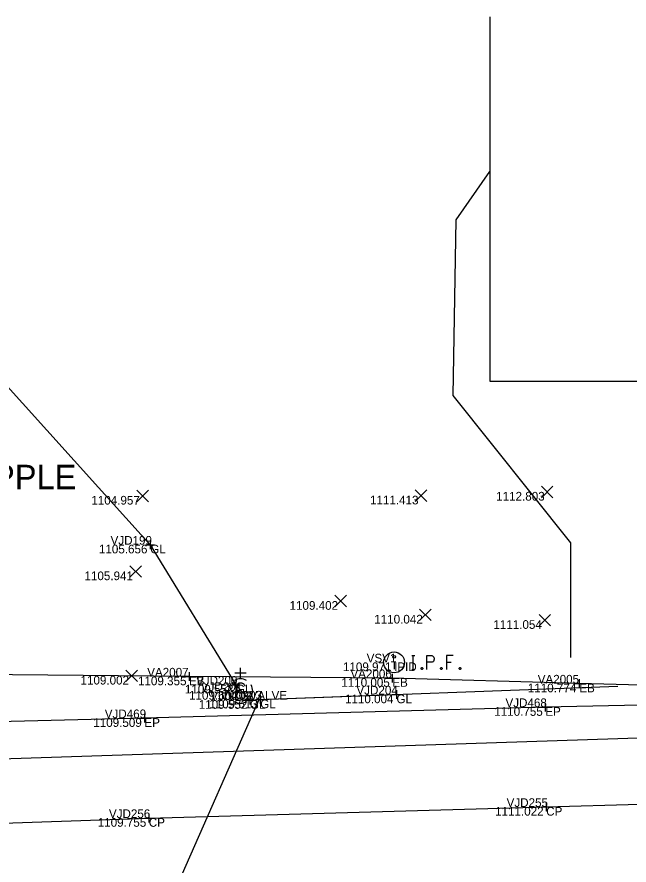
# Model space of a CAD drawing. Extents: x 1629915 to 1630675, y 484401 to 484601.
# Drawn here: x 1630425.3 to 1630495.7, y 484489.5 to 484587 of the extents above; entities that cross this region are included whole.
import ezdxf

# ---------------------------------------------------------------- set-up
doc = ezdxf.new("R2010")
doc.units = 0
for name, color, linetype in [('BD_X_Building', 7, 'Continuous'), ('PV_X_COP', 7, 'Continuous'), ('PV_X_EOP', 7, 'Continuous'), ('PV_X_Shoulder_Aggregate', 7, 'Continuous'), ('SV_X_Mon_Cells_Found', 7, 'Continuous'), ('SV_X_Random_Point', 7, 'Continuous'), ('SV_X_Shot_Marker', 7, 'Continuous'), ('SV_X_Text_Comment', 7, 'Continuous'), ('SV_X_Text_Elevation', 7, 'Continuous'), ('SV_X_Text_Name', 7, 'Continuous'), ('TX_X_20', 7, 'Continuous'), ('UT_X_Gas', 7, 'Continuous'), ('UT_X_Gas_Cells', 7, 'Continuous'), ('UT_X_Sanitary_Line', 7, 'Continuous')]:
    doc.layers.add(name, color=color, linetype=linetype)

msp = doc.modelspace()

# ---------------------------------------------------------------- linework, layer by layer
at = {"layer": 'BD_X_Building'}
msp.add_lwpolyline([(1630479.655, 484587.031), (1630479.655, 484545.173), (1630505.564, 484545.173), (1630505.564, 484546.173), (1630541.342, 484546.173), (1630541.342, 484585.235)], dxfattribs=at)
at = {"layer": 'PV_X_COP'}
msp.add_lwpolyline([(1630297.366, 484489.973), (1630308.553, 484490.492), (1630361.839, 484492.402), (1630403.565, 484493.662), (1630440.464, 484494.931), (1630486.149, 484496.207), (1630529.234, 484497.459), (1630568.325, 484498.484), (1630611.926, 484499.834), (1630649.713, 484500.97)], dxfattribs=at)
at = {"layer": 'PV_X_EOP'}
msp.add_lwpolyline([(1630649.544, 484512.337), (1630611.095, 484510.961), (1630568.311, 484509.618), (1630527.921, 484508.555), (1630486.049, 484507.685), (1630439.965, 484506.412), (1630403.104, 484505.478), (1630361.875, 484504.434), (1630301.74, 484502.192)], dxfattribs=at)
at = {"layer": 'PV_X_Shoulder_Aggregate'}
msp.add_lwpolyline([(1630609.295, 484512.622), (1630601.375, 484512.79), (1630594.371, 484513.028), (1630564.661, 484511.714), (1630557.668, 484510.64), (1630535.062, 484510.052), (1630513.96, 484509.735), (1630489.956, 484510.39), (1630468.462, 484511.02), (1630445.091, 484511.198), (1630420.706, 484511.45), (1630393.49, 484511.943), (1630369.145, 484512.288), (1630344.7, 484511.845), (1630320.659, 484510.608), (1630304.125, 484509.436), (1630303.965, 484508.981)], dxfattribs=at)
at = {"layer": 'SV_X_Mon_Cells_Found'}
msp.add_line((1630468.666, 484512.941), (1630468.666, 484512.058), dxfattribs=at)
for points in [[(1630470.696, 484513.624), (1630471.049, 484513.624)], [(1630470.872, 484512.024), (1630470.872, 484513.624)], [(1630472.438, 484512.024), (1630472.438, 484513.624), (1630472.967, 484513.624), (1630473.022, 484513.612), (1630473.099, 484513.586), (1630473.132, 484513.561), (1630473.165, 484513.536), (1630473.209, 484513.473), (1630473.242, 484513.41), (1630473.264, 484513.309), (1630473.264, 484513.158), (1630473.253, 484513.108), (1630473.231, 484513.032), (1630473.187, 484512.944), (1630473.143, 484512.906), (1630473.11, 484512.881), (1630473.055, 484512.856), (1630472.967, 484512.843), (1630472.438, 484512.843)], [(1630475.447, 484513.624), (1630474.686, 484513.624), (1630474.686, 484512.024)], [(1630471.831, 484512.239), (1630471.887, 484512.239), (1630471.92, 484512.213), (1630471.953, 484512.163), (1630471.953, 484512.1), (1630471.92, 484512.05), (1630471.887, 484512.024), (1630471.831, 484512.024), (1630471.798, 484512.05), (1630471.765, 484512.1), (1630471.765, 484512.163), (1630471.798, 484512.213), (1630471.831, 484512.239)], [(1630474.08, 484512.239), (1630474.135, 484512.239), (1630474.168, 484512.213), (1630474.201, 484512.163), (1630474.201, 484512.1), (1630474.168, 484512.05), (1630474.135, 484512.024), (1630474.08, 484512.024), (1630474.047, 484512.05), (1630474.014, 484512.1), (1630474.014, 484512.163), (1630474.047, 484512.213), (1630474.08, 484512.239)], [(1630474.686, 484512.843), (1630475.227, 484512.843)], [(1630476.23, 484512.239), (1630476.285, 484512.239), (1630476.318, 484512.213), (1630476.351, 484512.163), (1630476.351, 484512.1), (1630476.318, 484512.05), (1630476.285, 484512.024), (1630476.23, 484512.024), (1630476.196, 484512.05), (1630476.163, 484512.1), (1630476.163, 484512.163), (1630476.196, 484512.213), (1630476.23, 484512.239)], [(1630470.696, 484512.024), (1630471.049, 484512.024)]]:
    msp.add_lwpolyline(points, dxfattribs=at)
for centre, radius in [((1630468.666, 484512.824), 1.2), ((1630468.666, 484513.476), 0.16)]:
    msp.add_circle(centre, radius, dxfattribs=at)
at = {"layer": 'SV_X_Random_Point'}
for p, q in [((1630485.595, 484531.761), (1630486.928, 484533.096)), ((1630485.595, 484533.096), (1630486.928, 484531.761)), ((1630439.087, 484531.301), (1630440.421, 484532.636)), ((1630439.087, 484532.636), (1630440.421, 484531.301)), ((1630471.089, 484531.324), (1630472.423, 484532.659)), ((1630471.089, 484532.659), (1630472.423, 484531.324)), ((1630438.283, 484522.613), (1630439.617, 484523.948)), ((1630438.283, 484523.948), (1630439.617, 484522.613)), ((1630461.852, 484519.209), (1630463.186, 484520.544)), ((1630461.852, 484520.544), (1630463.186, 484519.209)), ((1630471.589, 484517.627), (1630472.922, 484518.962)), ((1630471.589, 484518.962), (1630472.922, 484517.627)), ((1630485.331, 484517.014), (1630486.664, 484518.349)), ((1630485.331, 484518.349), (1630486.664, 484517.014)), ((1630437.82, 484510.614), (1630439.154, 484511.949)), ((1630437.82, 484511.949), (1630439.154, 484510.614))]:
    msp.add_line(p, q, dxfattribs=at)
at = {"layer": 'SV_X_Shot_Marker'}
for p, q in [((1630440.635, 484526.86), (1630440.635, 484525.86)), ((1630440.135, 484526.36), (1630441.135, 484526.36)), ((1630440.635, 484526.36), (1630440.635, 484526.36)), ((1630445.091, 484511.698), (1630445.091, 484510.698)), ((1630468.462, 484511.52), (1630468.462, 484510.52)), ((1630444.591, 484511.198), (1630445.591, 484511.198)), ((1630445.091, 484511.198), (1630445.091, 484511.198)), ((1630450.487, 484510.753), (1630450.487, 484509.753)), ((1630467.962, 484511.02), (1630468.962, 484511.02)), ((1630468.462, 484511.02), (1630468.462, 484511.02)), ((1630489.456, 484510.39), (1630490.456, 484510.39)), ((1630489.956, 484510.89), (1630489.956, 484509.89)), ((1630489.956, 484510.39), (1630489.956, 484510.39)), ((1630449.987, 484510.253), (1630450.987, 484510.253)), ((1630450.487, 484510.253), (1630450.487, 484510.253)), ((1630468.94, 484509.634), (1630468.94, 484508.634)), ((1630451.583, 484508.491), (1630452.583, 484508.491)), ((1630452.083, 484508.991), (1630452.083, 484507.991)), ((1630452.083, 484508.491), (1630452.083, 484508.491)), ((1630452.778, 484508.551), (1630453.778, 484508.551)), ((1630453.278, 484509.051), (1630453.278, 484508.051)), ((1630453.278, 484508.551), (1630453.278, 484508.551)), ((1630468.44, 484509.134), (1630469.44, 484509.134)), ((1630468.94, 484509.134), (1630468.94, 484509.134)), ((1630485.549, 484507.685), (1630486.549, 484507.685)), ((1630486.049, 484508.185), (1630486.049, 484507.185)), ((1630486.049, 484507.685), (1630486.049, 484507.685)), ((1630439.465, 484506.412), (1630440.465, 484506.412)), ((1630439.965, 484506.912), (1630439.965, 484505.912)), ((1630439.965, 484506.412), (1630439.965, 484506.412)), ((1630486.149, 484496.707), (1630486.149, 484495.707)), ((1630485.649, 484496.207), (1630486.649, 484496.207)), ((1630486.149, 484496.207), (1630486.149, 484496.207)), ((1630439.964, 484494.931), (1630440.964, 484494.931)), ((1630440.464, 484495.431), (1630440.464, 484494.431)), ((1630440.464, 484494.931), (1630440.464, 484494.931))]:
    msp.add_line(p, q, dxfattribs=at)
at = {"layer": 'UT_X_Gas'}
for p, q in [((1630475.817, 484563.701), (1630479.655, 484569.276)), ((1630475.475, 484543.51), (1630475.817, 484563.701)), ((1630488.987, 484526.57), (1630475.475, 484543.51)), ((1630488.987, 484513.394), (1630488.987, 484526.57)), ((1630437.584, 484473.366), (1630453.173, 484508.545))]:
    msp.add_line(p, q, dxfattribs=at)
for points in [[(1630098.571, 484496.166), (1630109.658, 484497.037), (1630113.017, 484497.698), (1630113.953, 484498.758), (1630114.05, 484508.257), (1630114.557, 484509.569), (1630115.808, 484510.855), (1630129.42, 484519.99), (1630159.397, 484536.236), (1630181.581, 484547.984), (1630213.122, 484562.006), (1630240.482, 484573.334), (1630274.591, 484574.583), (1630290.006, 484572.984), (1630327.07, 484564.379), (1630366.658, 484567.361), (1630393.117, 484565.898), (1630419.955, 484549.235), (1630440.635, 484526.36), (1630450.487, 484510.253), (1630452.083, 484508.491), (1630453.278, 484508.551), (1630468.94, 484509.134)], [(1630098.571, 484496.166), (1630109.658, 484497.037), (1630113.017, 484497.698), (1630113.953, 484498.758), (1630114.05, 484508.257), (1630114.557, 484509.569), (1630115.808, 484510.855), (1630129.42, 484519.99), (1630159.397, 484536.236), (1630181.581, 484547.984), (1630213.122, 484562.006), (1630240.482, 484573.334), (1630274.591, 484574.583), (1630290.006, 484572.984), (1630327.07, 484564.379), (1630366.658, 484567.361), (1630393.117, 484565.898), (1630419.955, 484549.235), (1630440.635, 484526.36), (1630450.487, 484510.253), (1630452.083, 484508.491), (1630453.278, 484508.551), (1630494.384, 484510.081)]]:
    msp.add_lwpolyline(points, dxfattribs=at)
at = {"layer": 'UT_X_Gas_Cells'}
for p, q in [((1630451.647, 484511.572), (1630450.374, 484511.572)), ((1630451.011, 484510.937), (1630451.011, 484512.207)), ((1630451.011, 484509.537), (1630451.011, 484509.537))]:
    msp.add_line(p, q, dxfattribs=at)
msp.add_lwpolyline([(1630451.543, 484510.082), (1630451.529, 484510.153), (1630451.487, 484510.224), (1630451.416, 484510.295), (1630451.317, 484510.38), (1630451.246, 484510.408), (1630451.189, 484510.423), (1630451.104, 484510.437), (1630450.934, 484510.437), (1630450.863, 484510.423), (1630450.821, 484510.408), (1630450.764, 484510.38), (1630450.65, 484510.295), (1630450.58, 484510.196), (1630450.537, 484510.082), (1630450.509, 484509.927), (1630450.48, 484509.7), (1630450.48, 484509.402), (1630450.495, 484509.161), (1630450.551, 484508.977), (1630450.636, 484508.807), (1630450.707, 484508.75), (1630450.792, 484508.694), (1630450.948, 484508.637), (1630451.104, 484508.637), (1630451.26, 484508.665), (1630451.317, 484508.694), (1630451.373, 484508.722), (1630451.43, 484508.779), (1630451.487, 484508.864), (1630451.543, 484508.991), (1630451.543, 484509.345), (1630451.246, 484509.345)], dxfattribs=at)
for start, end in [(60.01836, 120.01574), (150.01836, 209.98164), (330.01836, 29.98164), (239.98426, 299.98164)]:
    msp.add_arc((1630451.011, 484509.537), 1.4, start, end, dxfattribs=at)
at = {"layer": 'UT_X_Sanitary_Line'}
msp.add_lwpolyline([(1629930.746, 484483.734), (1630048.132, 484488.308), (1630252.717, 484494.605), (1630261.76, 484567.793), (1630373.422, 484500.095), (1630654.857, 484509.349)], dxfattribs=at)

# ---------------------------------------------------------------- texts
at = {"layer": 'SV_X_Text_Comment'}
for s, p in [('GL', (1630440.635, 484525.36)), ('IPID', (1630468.666, 484511.824)), ('EB', (1630445.091, 484510.198)), ('GL', (1630450.487, 484509.253)), ('EB', (1630468.462, 484510.02)), ('EB', (1630489.956, 484509.39)), ('GVALVE', (1630451.011, 484508.537)), ('GL', (1630452.083, 484507.491)), ('GL', (1630453.278, 484507.551)), ('GL', (1630468.94, 484508.134)), ('EP', (1630486.049, 484506.685)), ('EP', (1630439.965, 484505.412)), ('CP', (1630486.149, 484495.207)), ('CP', (1630440.464, 484493.931))]:
    msp.add_text(s, height=1, dxfattribs=at).set_placement(p)
at = {"layer": 'SV_X_Text_Elevation'}
for s, p in [('1104.957', (1630433.86, 484530.969)), ('1111.413', (1630465.894, 484530.992)), ('1112.803', (1630480.399, 484531.429)), ('1105.656', (1630434.733, 484525.36)), ('1105.941', (1630433.07, 484522.281)), ('1109.402', (1630456.648, 484518.876)), ('1110.042', (1630466.384, 484517.295)), ('1111.054', (1630480.077, 484516.682)), ('1109.971', (1630462.786, 484511.824)), ('1109.002', (1630432.616, 484510.281)), ('1109.355', (1630439.222, 484510.198)), ('1109.552', (1630444.615, 484509.253)), ('1110.005', (1630462.593, 484510.02)), ('1110.774', (1630484.036, 484509.39)), ('1109.604', (1630445.09, 484508.537)), ('1109.552', (1630446.211, 484507.491)), ('1109.613', (1630447.416, 484507.551)), ('1110.004', (1630463.019, 484508.134)), ('1110.755', (1630480.181, 484506.685)), ('1109.509', (1630434.084, 484505.412)), ('1111.022', (1630480.278, 484495.207)), ('1109.755', (1630434.596, 484493.931))]:
    msp.add_text(s, height=1, dxfattribs=at).set_placement(p)
at = {"layer": 'SV_X_Text_Name'}
for s, p in [('VJD199', (1630436.072, 484526.36)), ('VSV1', (1630465.515, 484512.824)), ('VA2007', (1630440.284, 484511.198)), ('VJD200', (1630445.893, 484510.253)), ('VA2006', (1630463.647, 484511.02)), ('VA2005', (1630485.175, 484510.39)), ('VJD201', (1630446.449, 484509.537)), ('VJD202', (1630447.53, 484508.491)), ('VJD203', (1630448.734, 484508.551)), ('VJD204', (1630464.338, 484509.134)), ('VJD468', (1630481.469, 484507.685)), ('VJD469', (1630435.402, 484506.412)), ('VJD255', (1630481.599, 484496.207)), ('VJD256', (1630435.88, 484494.931))]:
    msp.add_text(s, height=1, dxfattribs=at).set_placement(p)
at = {"layer": 'TX_X_20'}
msp.add_text('2" APPLE', height=2.8, dxfattribs=at).set_placement((1630415.616, 484532.743))

doc.saveas('drawing.dxf')
